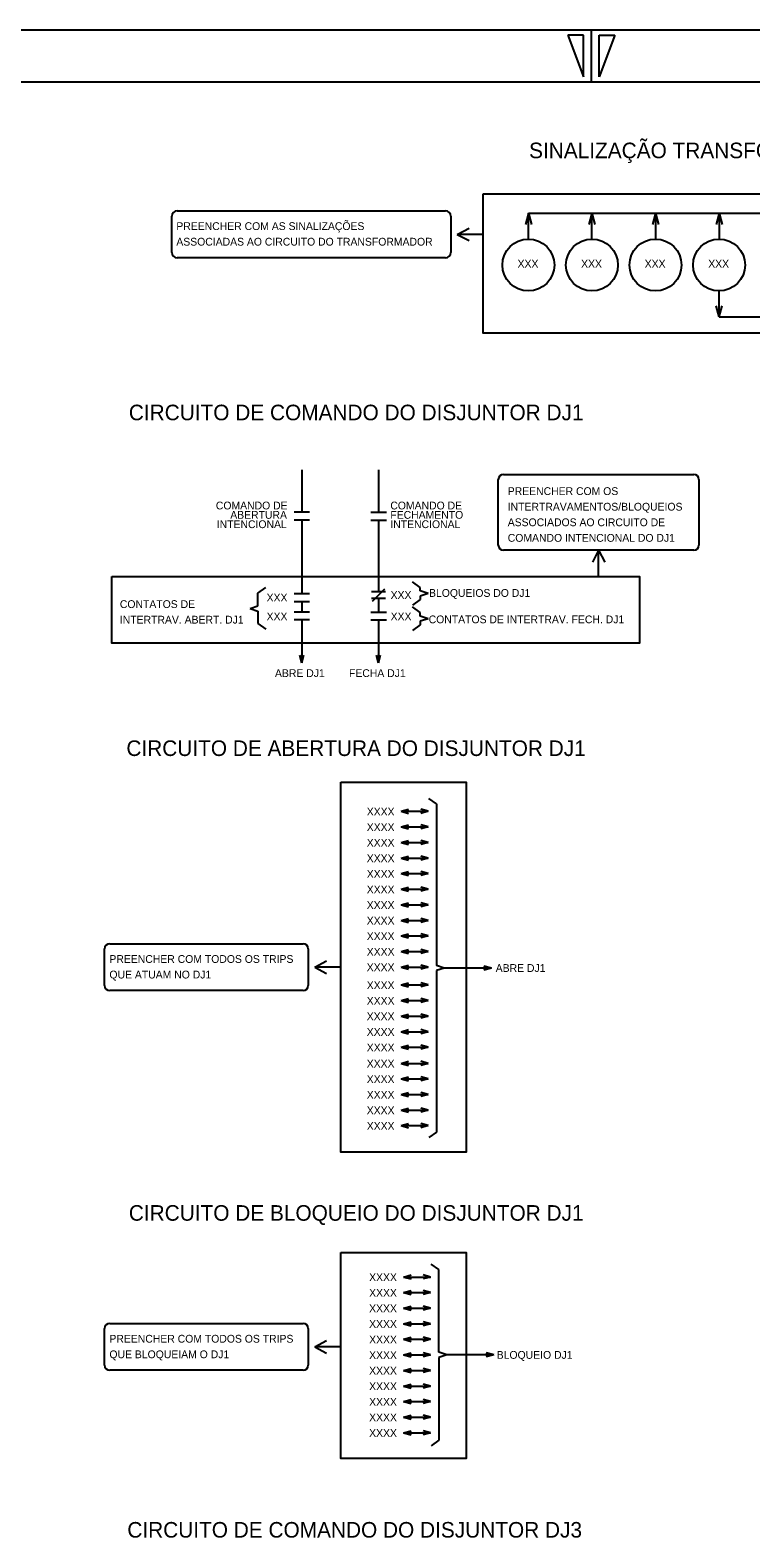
# Model space of a CAD drawing. Extents: x 400 to 1404, y 358 to 952.
# Drawn here: x 1110.5 to 1249.3, y 661.6 to 952 of the extents above; entities that cross this region are included whole.
import ezdxf

# ---------------------------------------------------------------- set-up
doc = ezdxf.new("R2010")
doc.units = 0
doc.layers.add('New Level (0)', color=7, linetype='Continuous')

# ---------------------------------------------------------------- blocks, each defined once
blk = doc.blocks.new('39')
for p, q in [((0, 0), (1.45, 0.39)), ((0, 0), (5.22, 0)), ((0, 0), (1.45, -0.39)), ((5.22, 0), (3.77, 0.39)), ((5.22, 0), (3.77, -0.39))]:
    blk.add_line(p, q)

msp = doc.modelspace()

# ---------------------------------------------------------------- linework, layer by layer
for p, q in [((1206.46, 916.72), (1205.87, 914.55)), ((1206.46, 911.72), (1206.46, 916.72)), ((1206.46, 916.72), (1265.58, 916.72)), ((1206.46, 916.72), (1207.04, 914.55)), ((1218.7, 916.72), (1218.12, 914.55)), ((1218.7, 911.72), (1218.7, 916.72)), ((1218.7, 916.72), (1219.28, 914.55)), ((1230.94, 916.72), (1230.36, 914.55)), ((1230.94, 916.72), (1230.94, 911.72)), ((1230.94, 916.72), (1231.53, 914.55)), ((1243.19, 916.72), (1242.6, 914.55)), ((1243.19, 916.72), (1243.19, 911.72)), ((1243.19, 916.72), (1243.77, 914.55)), ((1243.19, 896.72), (1243.19, 901.72)), ((1243.19, 896.72), (1242.6, 898.89)), ((1243.19, 896.72), (1243.77, 898.89)), ((1243.19, 896.72), (1265.58, 896.72)), ((1162.82, 867.28), (1162.82, 859.1)), ((1177.61, 867.28), (1177.61, 859.1)), ((1164.32, 859.1), (1161.32, 859.1)), ((1164.32, 857.6), (1161.32, 857.6)), ((1162.82, 857.6), (1162.82, 843.36)), ((1176.11, 859.1), (1179.11, 859.1)), ((1176.11, 857.6), (1179.11, 857.6)), ((1177.61, 857.6), (1177.61, 843.86)), ((1185.62, 844.64), (1184.12, 845.72)), ((1154.36, 843.55), (1155.86, 844.63)), ((1154.36, 841.08), (1154.36, 843.55)), ((1164.32, 843.36), (1161.32, 843.36)), ((1176.26, 843.86), (1178.96, 843.86)), ((1178.96, 842.51), (1176.26, 842.51)), ((1176.42, 842), (1178.8, 844.38)), ((1177.61, 842.36), (1177.61, 839.86)), ((1185.62, 842.27), (1184.12, 841.19)), ((1185.62, 843.96), (1185.62, 844.64)), ((1187.12, 843.46), (1185.62, 843.96)), ((1187.12, 843.46), (1185.62, 842.96)), ((1185.62, 842.96), (1185.62, 842.27)), ((1152.86, 840.58), (1154.36, 841.08)), ((1152.86, 840.58), (1154.36, 840.08)), ((1154.36, 840.08), (1154.36, 837.68)), ((1164.32, 841.86), (1161.32, 841.86)), ((1164.32, 839.86), (1161.32, 839.86)), ((1162.82, 841.86), (1162.82, 839.86)), ((1176.11, 839.86), (1179.11, 839.86)), ((1176.11, 839.86), (1179.11, 839.86)), ((1185.62, 839.78), (1184.12, 840.87)), ((1185.62, 839.1), (1185.62, 839.78)), ((1154.36, 837.68), (1155.86, 836.6)), ((1164.32, 838.36), (1161.32, 838.36)), ((1162.82, 838.36), (1162.82, 830.12)), ((1176.11, 838.36), (1179.11, 838.36)), ((1176.11, 838.36), (1179.11, 838.36)), ((1177.61, 838.36), (1177.61, 830.12)), ((1185.62, 837.42), (1184.12, 836.33)), ((1187.12, 838.6), (1185.62, 839.1)), ((1187.12, 838.6), (1185.62, 838.1)), ((1185.62, 838.1), (1185.62, 837.42)), ((1162.82, 830.12), (1162.43, 831.57)), ((1162.82, 830.12), (1163.21, 831.57)), ((1177.61, 830.12), (1177.22, 831.57)), ((1177.61, 830.12), (1178, 831.57)), ((1181.94, 801.5), (1183.39, 801.89)), ((1181.94, 801.5), (1187.16, 801.5)), ((1181.94, 801.5), (1183.39, 801.11)), ((1187.16, 801.5), (1185.71, 801.89)), ((1187.16, 801.5), (1185.71, 801.11)), ((1188.76, 802.92), (1187.26, 804)), ((1188.76, 802.92), (1188.76, 771.82)), ((1181.94, 798.5), (1183.39, 798.89)), ((1187.16, 798.5), (1185.71, 798.89)), ((1181.94, 798.5), (1187.16, 798.5)), ((1181.94, 798.5), (1183.39, 798.11)), ((1181.94, 795.5), (1183.39, 795.89)), ((1187.16, 798.5), (1185.71, 798.11)), ((1187.16, 795.5), (1185.71, 795.89)), ((1181.94, 795.5), (1187.16, 795.5)), ((1181.94, 795.5), (1183.39, 795.11)), ((1187.16, 795.5), (1185.71, 795.11)), ((1190.26, 771.32), (1188.76, 771.82)), ((1190.26, 771.32), (1188.76, 770.82)), ((1188.76, 770.82), (1188.76, 739.73)), ((1199.32, 771.32), (1190.26, 771.32)), ((1199.32, 771.32), (1197.87, 771.71)), ((1199.32, 771.32), (1197.87, 770.94)), ((1181.94, 768.06), (1183.39, 768.44)), ((1181.94, 768.06), (1187.16, 768.06)), ((1181.94, 768.06), (1183.39, 767.67)), ((1187.16, 768.06), (1185.71, 768.44)), ((1187.16, 768.06), (1185.71, 767.67)), ((1181.94, 752.96), (1183.39, 753.35)), ((1181.94, 752.96), (1187.16, 752.96)), ((1181.94, 752.96), (1183.39, 752.57)), ((1187.16, 752.96), (1185.71, 753.35)), ((1187.16, 752.96), (1185.71, 752.57)), ((1188.76, 739.73), (1187.26, 738.65)), ((1182.41, 711.81), (1183.86, 712.2)), ((1182.41, 711.81), (1187.63, 711.81)), ((1182.41, 711.81), (1183.86, 711.43)), ((1187.63, 711.81), (1186.18, 712.2)), ((1187.63, 711.81), (1186.18, 711.43)), ((1189.23, 713.23), (1187.73, 714.31)), ((1189.23, 697.31), (1189.23, 713.23)), ((1182.41, 705.81), (1183.86, 706.2)), ((1182.41, 705.81), (1187.63, 705.81)), ((1182.41, 705.81), (1183.86, 705.43)), ((1187.63, 705.81), (1186.18, 706.2)), ((1187.63, 705.81), (1186.18, 705.43)), ((1190.73, 696.81), (1189.23, 697.31)), ((1199.79, 696.81), (1198.34, 697.2)), ((1190.73, 696.81), (1189.23, 696.31)), ((1189.23, 696.31), (1189.23, 680.4)), ((1199.79, 696.81), (1190.73, 696.81)), ((1199.79, 696.81), (1198.34, 696.43)), ((1189.23, 680.4), (1187.73, 679.31))]:
    msp.add_line(p, q)
for centre in [(1206.46, 906.72), (1218.7, 906.72), (1230.94, 906.72), (1243.19, 906.72)]:
    msp.add_circle(centre, 5)
at = {"layer": 'New Level (0)'}
for p, q in [((1403.58, 951.96), (562.58, 951.96)), ((1403.58, 951.96), (562.58, 951.96)), ((1217.08, 950.96), (1214.08, 950.96)), ((1214.08, 950.96), (1217.08, 942.96)), ((1217.08, 942.96), (1217.08, 950.96)), ((1218.58, 951.96), (1218.58, 941.96)), ((1220.08, 942.96), (1220.08, 950.96)), ((1220.08, 950.96), (1223.08, 950.96)), ((1223.08, 950.96), (1220.08, 942.96)), ((1393.58, 941.96), (572.58, 941.96)), ((1137.78, 909.11), (1137.78, 916.14)), ((1138.78, 917.14), (1160.63, 917.14)), ((1160.63, 917.14), (1190.51, 917.14)), ((1191.51, 916.14), (1191.51, 909.11)), ((1192.74, 912.63), (1195.04, 913.84)), ((1197.77, 912.63), (1192.74, 912.63)), ((1192.74, 912.63), (1195.04, 911.42)), ((1190.51, 908.11), (1138.78, 908.11)), ((1200.66, 852.79), (1200.66, 865.38)), ((1201.66, 866.38), (1238.32, 866.38)), ((1239.32, 865.38), (1239.32, 852.79)), ((1238.32, 851.79), (1201.66, 851.79)), ((1219.99, 851.79), (1218.78, 849.49)), ((1219.99, 846.76), (1219.99, 851.79)), ((1219.99, 851.79), (1221.2, 849.49)), ((1125.82, 776.01), (1133.17, 776.01)), ((1133.17, 776.01), (1163.05, 776.01)), ((1124.82, 767.98), (1124.82, 775.01)), ((1164.05, 775.01), (1164.05, 767.98)), ((1165.29, 771.5), (1167.58, 772.71)), ((1170.32, 771.5), (1165.29, 771.5)), ((1165.29, 771.5), (1167.58, 770.29)), ((1163.05, 766.98), (1125.82, 766.98)), ((1125.82, 702.87), (1133.17, 702.87)), ((1133.17, 702.87), (1163.05, 702.87)), ((1124.82, 694.84), (1124.82, 701.87)), ((1164.05, 701.87), (1164.05, 694.84)), ((1165.29, 698.36), (1167.58, 699.57)), ((1170.32, 698.36), (1165.29, 698.36)), ((1165.29, 698.36), (1167.58, 697.15)), ((1163.05, 693.84), (1125.82, 693.84))]:
    msp.add_line(p, q, dxfattribs=at)
for points in [[(1197.77, 920.41), (1261.69, 920.41), (1261.69, 893.59), (1197.77, 893.59)], [(1126.19, 846.76), (1227.89, 846.76), (1227.89, 833.87), (1126.19, 833.87)], [(1170.32, 807.12), (1194.45, 807.12), (1194.45, 735.87), (1170.32, 735.87)], [(1170.32, 716.5), (1194.45, 716.5), (1194.45, 676.86), (1170.32, 676.86)]]:
    msp.add_lwpolyline(points, close=True, dxfattribs=at)
for centre, start, end in [((1138.78, 916.14), 90, 180), ((1190.51, 916.14), 0, 90), ((1138.78, 909.11), 180, 270), ((1190.51, 909.11), 270, 0), ((1201.66, 865.38), 90, 180), ((1238.32, 865.38), 0, 90), ((1201.66, 852.79), 180, 270), ((1238.32, 852.79), 270, 0), ((1125.82, 775.01), 90, 180), ((1163.05, 775.01), 0, 90), ((1125.82, 767.98), 180, 270), ((1163.05, 767.98), 270, 0), ((1125.82, 701.87), 90, 180), ((1163.05, 701.87), 0, 90), ((1125.82, 694.84), 180, 270), ((1163.05, 694.84), 270, 0)]:
    msp.add_arc(centre, 1, start, end, dxfattribs=at)

# ---------------------------------------------------------------- block references
for p in [(1181.94, 792.5), (1181.94, 789.5), (1181.94, 786.5), (1181.94, 783.5), (1181.94, 780.5), (1181.94, 777.5), (1181.94, 774.5), (1181.94, 771.5), (1181.94, 765.06), (1181.94, 762.06), (1181.94, 759.06), (1181.94, 756.06), (1181.94, 749.96), (1181.94, 746.96), (1181.94, 743.96), (1181.94, 740.96), (1182.41, 708.81), (1182.41, 702.81), (1182.41, 699.81), (1182.41, 696.81), (1182.41, 693.81), (1182.41, 690.81), (1182.41, 687.81), (1182.41, 684.81), (1182.41, 681.81)]:
    msp.add_blockref('39', p)

# ---------------------------------------------------------------- texts
for s, height, p in [('SINALIZAÇÃO TRANSFORMADOR T1', 3, (1206.59, 927.29)), ('PREENCHER COM AS SINALIZAÇÕES', 1.5, (1138.64, 913.46)), ('ASSOCIADAS AO CIRCUITO DO TRANSFORMADOR', 1.5, (1138.64, 910.46)), ('XXX', 1.5, (1204.37, 906.22)), ('XXX', 1.5, (1216.61, 906.22)), ('XXX', 1.5, (1228.86, 906.22)), ('XXX', 1.5, (1241.1, 906.22)), ('CIRCUITO DE COMANDO DO DISJUNTOR DJ1', 3, (1129.49, 876.82)), ('PREENCHER COM OS ', 1.5, (1202.48, 862.42)), ('COMANDO DE', 1.5, (1146.25, 859.65)), ('COMANDO DE ', 1.5, (1179.86, 859.65)), ('INTERTRAVAMENTOS/BLOQUEIOS', 1.5, (1202.48, 859.42)), (' INTENCIONAL', 1.5, (1145.87, 856.05)), (' ABERTURA', 1.5, (1148.47, 857.85)), ('FECHAMENTO ', 1.5, (1179.86, 857.85)), ('INTENCIONAL', 1.5, (1179.86, 856.05)), ('ASSOCIADOS AO CIRCUITO DE ', 1.5, (1202.48, 856.42)), ('COMANDO INTENCIONAL DO DJ1', 1.5, (1202.48, 853.42)), ('CONTATOS DE ', 1.5, (1127.76, 840.66)), ('XXX', 1.5, (1156.03, 841.92)), ('XXX', 1.5, (1179.92, 842.41)), ('BLOQUEIOS DO DJ1', 1.5, (1187.32, 842.81)), ('XXX', 1.5, (1156.03, 838.29)), ('XXX', 1.5, (1179.92, 838.29)), ('CONTATOS DE INTERTRAV. FECH. DJ1', 1.5, (1187.25, 837.72)), ('INTERTRAV. ABERT. DJ1', 1.5, (1127.76, 837.66)), ('ABRE DJ1', 1.5, (1157.64, 827.37)), ('FECHA DJ1', 1.5, (1171.9, 827.37)), ('CIRCUITO DE ABERTURA DO DISJUNTOR DJ1', 3, (1129.02, 812.16)), ('XXXX', 1.5, (1175.32, 800.7)), ('XXXX', 1.5, (1175.32, 797.7)), ('XXXX', 1.5, (1175.32, 794.7)), ('XXXX', 1.5, (1175.32, 791.7)), ('XXXX', 1.5, (1175.32, 788.7)), ('XXXX', 1.5, (1175.32, 785.7)), ('XXXX', 1.5, (1175.32, 782.7)), ('XXXX', 1.5, (1175.32, 779.7)), ('XXXX', 1.5, (1175.32, 776.7)), ('PREENCHER COM TODOS OS TRIPS', 1.5, (1125.75, 772.31)), ('XXXX', 1.5, (1175.32, 773.7)), ('QUE ATUAM NO DJ1', 1.5, (1125.75, 769.31)), ('XXXX', 1.5, (1175.32, 770.7)), ('ABRE DJ1', 1.5, (1200.16, 770.57)), ('XXXX', 1.5, (1175.32, 767.26)), ('XXXX', 1.5, (1175.32, 764.26)), ('XXXX', 1.5, (1175.32, 761.26)), ('XXXX', 1.5, (1175.32, 758.26)), ('XXXX', 1.5, (1175.32, 755.26)), ('XXXX', 1.5, (1175.32, 752.16)), ('XXXX', 1.5, (1175.32, 749.16)), ('XXXX', 1.5, (1175.32, 746.16)), ('XXXX', 1.5, (1175.32, 743.16)), ('XXXX', 1.5, (1175.32, 740.16)), ('CIRCUITO DE BLOQUEIO DO DISJUNTOR DJ1', 3, (1129.49, 722.65)), ('XXXX', 1.5, (1175.78, 711.02)), ('XXXX', 1.5, (1175.78, 708.02)), ('XXXX', 1.5, (1175.78, 705.02)), ('XXXX', 1.5, (1175.78, 702.02)), ('PREENCHER COM TODOS OS TRIPS', 1.5, (1125.75, 699.17)), ('XXXX', 1.5, (1175.78, 699.02)), ('QUE BLOQUEIAM O DJ1', 1.5, (1125.75, 696.17)), ('XXXX', 1.5, (1175.78, 696.02)), ('BLOQUEIO DJ1', 1.5, (1200.36, 696.06)), ('XXXX', 1.5, (1175.78, 693.02)), ('XXXX', 1.5, (1175.78, 690.02)), ('XXXX', 1.5, (1175.78, 687.02)), ('XXXX', 1.5, (1175.78, 684.02)), ('XXXX', 1.5, (1175.78, 681.02)), ('CIRCUITO DE COMANDO DO DISJUNTOR DJ3', 3, (1129.2, 661.62))]:
    msp.add_text(s, height=height).set_placement(p)

doc.saveas('drawing.dxf')
